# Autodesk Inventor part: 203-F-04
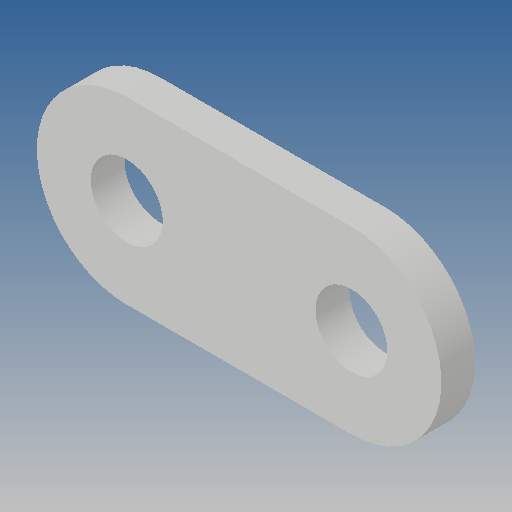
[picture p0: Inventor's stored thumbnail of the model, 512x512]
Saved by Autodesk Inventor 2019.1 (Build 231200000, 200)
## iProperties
Created: 2011-05
Part Number: 203-F-04
Material: Ogólny
Document SubType Name: Modeling
Designer: CADENGINEERING4
Density: 1 g/cm^3
Appearance: Domyślna
Author: CADENGINEERING4
Revision Number: ÈÎºÎ
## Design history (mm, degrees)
feature "À­Éì1"
node "Bryła1"
